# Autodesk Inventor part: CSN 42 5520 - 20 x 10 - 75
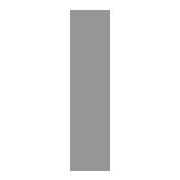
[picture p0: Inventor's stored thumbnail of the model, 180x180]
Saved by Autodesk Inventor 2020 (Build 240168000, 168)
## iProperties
IsCustomPart: 1
Created: 2019-01
Part Number: CSN 42 5520 - 20 x 10 - 75
Material: Ocel, měkká
Description: Tyč
Document SubType Name: Modeling
Standard: CSN 42 5520
Designer: doma
Standards Organization: CSN
Language: cs-CZ
Size Designation: 20 x 10 - 75
Categories: <MemberInstance><Categories><Category DisplayName="Konstrukční profily" InternalName="089c4875-fa83-4c05-b084-43b9cc11f5ed" Mnemonic="GRDR"><CategoryParameter D
Stock Number: 20 x 10
Density: 7.85 g/cm^3
Appearance: Pololeštěná
Mass: 97.5798 g
Surface Area: 57.6761 cm^2
Volume: 12.4305 cm^3
G_L: 75,000 mm
Author: doma
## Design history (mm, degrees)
node "Počáteční rovina"
node "Koncová rovina"
sketch "Náčrt"
  geometry: L1 (5, -10)-(-5, -10); L2 (-5, -10)-(-5, 10); L3 (-5, 10)-(5, 10); L4 (5, 10)-(5, -10); L5 (-6, 0)-(8, 0); L6 (0, -30)-(0, 40); L7 (0, 54)-(0, -44) reference; L8 (-9.2, 0)-(13.2, 0) reference
  constraints: 12 end point, 2 collinear, 2 parallel, 1 horizontal, 1 perpendicular
  dimensions: "d0" = 20 distance between parallel lines of L3 L1 (= G_W); "d1" = 10 distance between parallel lines of L4 L2 (= G_H); "d4" = 5 distance between parallel lines of L6 L4 (= 0.5 x d1); "d5" = 10 distance between parallel lines of L5 L3 (= 0.5 x d0)
extrude "Těleso" new body sketch "Náčrt" stored distance "d2" = 75 (= G_L); taper "d3" = 0 deg
node "Driven Length"
  sketch "Sketch3"
    geometry: L1 (0, 0)-(10, 0) reference
    constraints: 2 end point, 1 horizontal
  workplane "Work Plane3"
  sketch "Sketch4"
    geometry: L1 (-2, 0)-(12, 0) reference; L2 (-2, 75)-(12, 75) reference
    dimensions: "d9" = 75 distance between parallel lines of L1 L2 (derived)
sketch "Náčrt5"
  geometry: L1 (0, 20)-(0, 0) reference; L2 (-35, 9.5)-(35, 9.5); L3 (35, 9.5)-(35, 10.5); L4 (35, 10.5)-(-35, 10.5); L5 (-35, 10.5)-(-35, 9.5); L6 (0, 0)-(0, 20) reference; L7 (-35, 9.5)-(35, 10.5); L8 (35, 9.5)-(-35, 10.5); L9 (75, 20)-(75, 0) reference; C1 r 7 at (20, 10); C2 r 2.1 at (67, 10); 8 further points
  constraints: 12 end point, 3 midpoint, 2 centre point, 2 parallel, 1 horizontal, 1 perpendicular
  dimensions: "d10" = 14 diameter of C1; "d11" = 20 distance from line of L1 C1.centre; "d12" = 70 distance of L4.end L3.end; "d13" = 1 distance of L3.end L2.end; "d14" = 4.2 diameter of C2; "d15" = 8 distance from line of C2.centre L9
extrude "Vysunutí2" cut sketch "Náčrt5" extent not by distance; stored distance "d16" = 0; taper "d17" = 0 deg
sketch "Náčrt6"
  geometry: L1 (10, 61.982)-(0, 61.982) reference; L2 (10, 75)-(0, 75) reference; C1 r 3 at (5, 69); 1 further point
  constraints: 1 centre point
  dimensions: "d18" = 6 diameter of C1; "d19" = 6 distance from line of L2 C1.centre
extrude "Vysunutí3" cut sketch "Náčrt6" extent not by distance; stored distance "d20" = 0; taper "d21" = 0 deg
feature "Závit1" dims "d22" = 10, "d23" = 0
body "Solid1"
other parameters: "G_W" = 20 [user parameter; used in 1 equation term], "G_H" = 10 [user parameter; used in 1 equation term], "G_L" = 75 (= d9) [user parameter; used in 1 equation term], "G_OFFSET_START" = 0 [user parameter; used in 1 equation term], "G_OFFSET_END" = 0 [user parameter; used in 1 equation term], "d6" = 0 (computed from G_OFFSET_START), "d7" = 75 (= G_OFFSET_END + B_L), "B_L" = 75 [user parameter; used in 1 equation term], "d8" = 90 deg
